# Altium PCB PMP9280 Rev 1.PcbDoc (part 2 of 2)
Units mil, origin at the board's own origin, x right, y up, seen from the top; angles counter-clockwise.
Board outline 4050 x 2360 mil, 4 copper layers (Top Layer, MidLayer1, MidLayer2, Bottom Layer), stack 61.2 mil thick; 80 components, 27 nets, 139 pads, 275 vias.
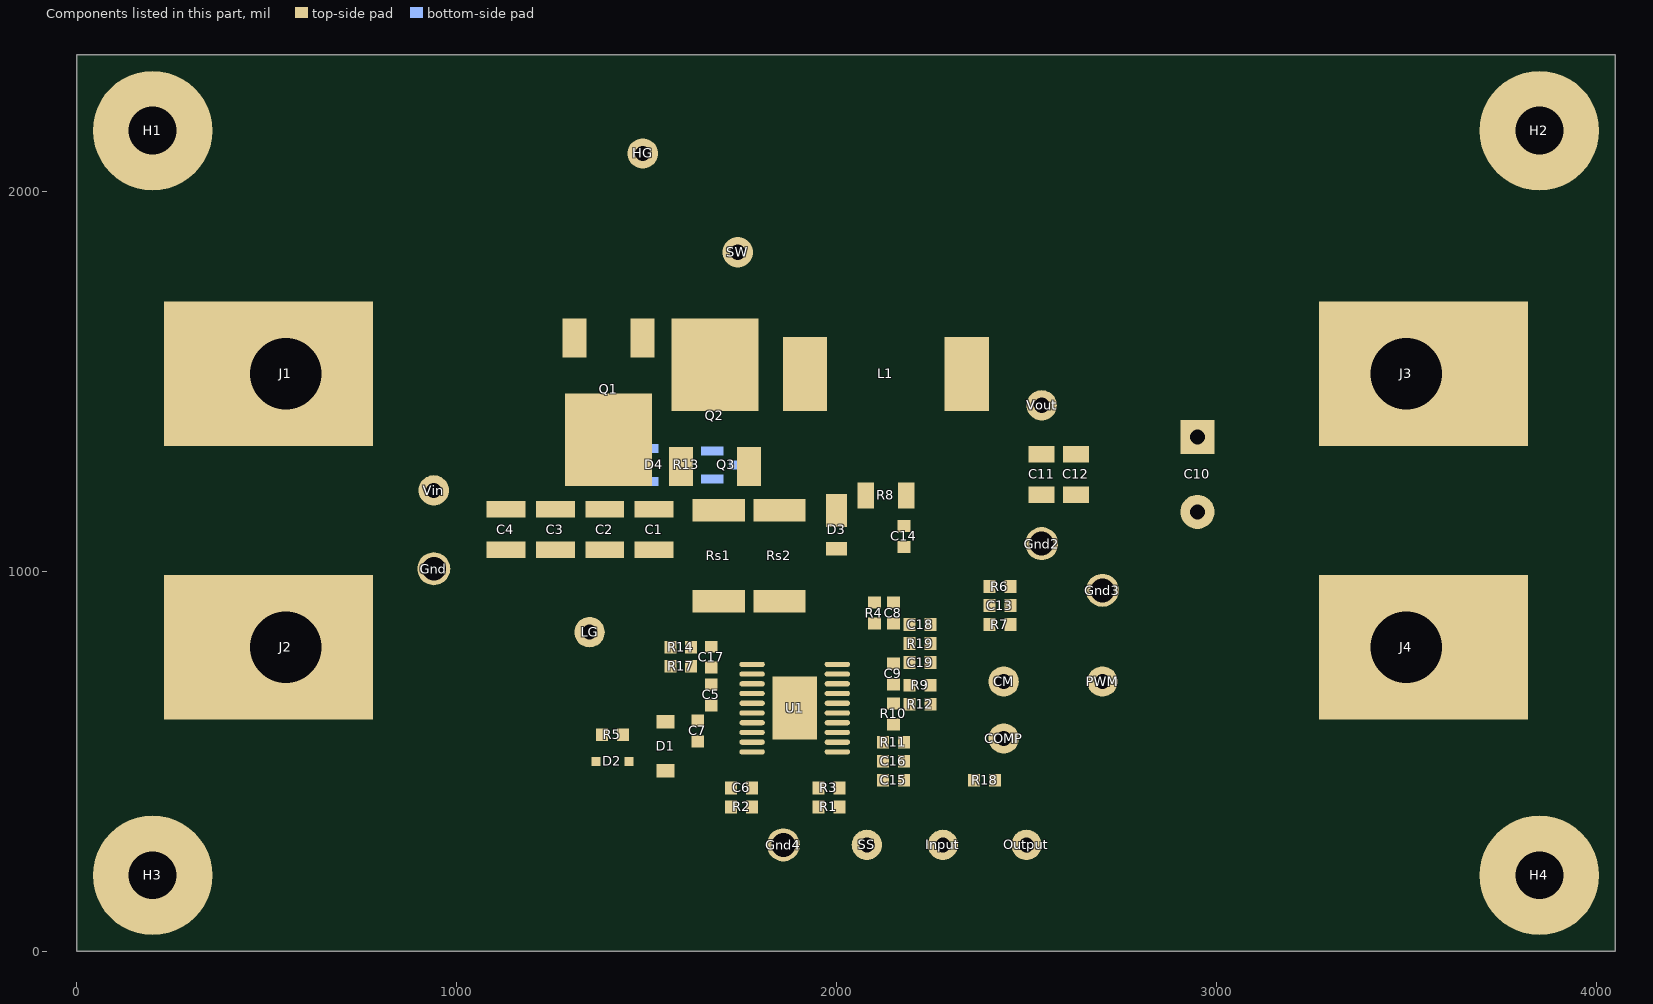
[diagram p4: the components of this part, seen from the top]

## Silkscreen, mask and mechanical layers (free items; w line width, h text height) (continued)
M12 Stackup:
  drawing of 295 lines, arcs and shapes, not listed
  text "Layer" at 5943.24,4323.04 h60
  text "Name" at 6353.15,4323.04 h60
  text "Material" at 7282.9,4323.04 h60
  text "Thickness" at 8142.66,4323.04 h60
  text "Constant" at 8792.5,4323.04 h60
  text "Board Layer Stack" at 9362.36,4323.04 h60
  text "1" at 5943.24,4203.04 h60
  text "Top Overlay" at 6353.15,4203.04 h60
  text "2" at 5943.24,4083.04 h60
  text "Top Solder" at 6353.15,4083.04 h60
  text "Solder Resist" at 7282.9,4083.04 h60
  text "0.40mil" at 8142.66,4083.04 h60
  text "3.5" at 8792.5,4083.04 h60
  text "3" at 5943.24,3963.04 h60
  text "Top Layer" at 6353.15,3963.04 h60
  text "Copper" at 7282.9,3963.04 h60
  text "1.40mil" at 8142.66,3963.04 h60
  text "4" at 5943.24,3843.04 h60
  text "Dielectric1" at 6353.15,3843.04 h60
  text "FR-4" at 7282.9,3843.04 h60
  text "12.60mil" at 8142.66,3843.04 h60
  text "4.8" at 8792.5,3843.04 h60
  text "5" at 5943.24,3723.04 h60
  text "MidLayer1" at 6353.15,3723.04 h60
  text "Copper" at 7282.9,3723.04 h60
  text "1.40mil" at 8142.66,3723.04 h60
  text "6" at 5943.24,3603.04 h60
  text "Dielectric2" at 6353.15,3603.04 h60
  text "FR-4" at 7282.9,3603.04 h60
  text "30.40mil" at 8142.66,3603.04 h60
  text "4.8" at 8792.5,3603.04 h60
  text "7" at 5943.24,3483.04 h60
  text "MidLayer2" at 6353.15,3483.04 h60
  text "Copper" at 7282.9,3483.04 h60
  text "1.40mil" at 8142.66,3483.04 h60
  text "8" at 5943.24,3363.04 h60
  text "Dielectric3" at 6353.15,3363.04 h60
  text "FR-4" at 7282.9,3363.04 h60
  text "12.60mil" at 8142.66,3363.04 h60
  text "4.8" at 8792.5,3363.04 h60
  text "9" at 5943.24,3243.04 h60
  text "Bottom Layer" at 6353.15,3243.04 h60
  text "Copper" at 7282.9,3243.04 h60
  text "1.40mil" at 8142.66,3243.04 h60
  text "10" at 5943.24,3123.04 h60
  text "Bottom Solder" at 6353.15,3123.04 h60
  text "Solder Resist" at 7282.9,3123.04 h60
  text "0.40mil" at 8142.66,3123.04 h60
  text "3.5" at 8792.5,3123.04 h60
  text "11" at 5943.24,3003.04 h60
  text "Bottom Overlay" at 6353.15,3003.04 h60
  text ".Layer_Name" at 17,-1418.49 h60
M13 Component Bodies Top:
  text ".Layer_Name" at 17,-1418.49 h60
M14 Component Bodies Bottom:
  text ".Layer_Name" at 17,-1418.49 h60
M15 Courtyards Top:
  text ".Layer_Name" at 17,-1418.49 h60
M16 Courtyards Bottom:
  text ".Layer_Name" at 17,-1418.49 h60
Drill Drawing:
  circle w10: c4856.73,1551.58 r16.58
  circle w10: c4856.73,1551.58 r27.63
  lines w10: 4829.1,1330.54 4884.36,1330.54 4856.73,1275.28 4829.1,1330.54 ; 4829.1,1413.43 4842.91,1413.43 4856.73,1399.62 4870.54,1413.43 4884.36,1413.43 4870.54,1427.25 4884.36,1441.06 4870.54,1441.06 4856.73,1454.88 4842.91,1441.06 4829.1,1441.06 4842.91,1427.25 4829.1,1413.43 ; 4829.1,1648.29 4884.36,1648.29 4884.36,1703.55 4829.1,1703.55 4829.1,1648.29 ; 4829.1,1786.44 4842.91,1786.44 4842.91,1772.62 4870.54,1772.62 4870.54,1786.44 4884.36,1786.44 4884.36,1814.07 4870.54,1814.07 4870.54,1827.89 4842.91,1827.89 4842.91,1814.07 4829.1,1814.07 4829.1,1786.44 ; 4829.1,2021.3 4829.1,2035.11 4842.91,2048.93 4829.1,2062.74 4829.1,2076.56 4842.91,2076.56 4856.73,2062.74 4870.54,2076.56 4884.36,2076.56 4884.36,2062.74 4870.54,2048.93 4884.36,2035.11 4884.36,2021.3 4870.54,2021.3 4856.73,2035.11 4842.91,2021.3 4829.1,2021.3 ; 4829.1,2145.63 4856.73,2159.45 4884.36,2145.63 4870.54,2173.26 4884.36,2200.89 4856.73,2187.08 4829.1,2200.89 4842.91,2173.26 4829.1,2145.63 ; 4840.15,1319.49 4873.3,1319.49 4856.73,1286.34 4840.15,1319.49 ; 4840.15,1418.96 4848.44,1418.96 4856.73,1410.67 4865.02,1418.96 4873.3,1418.96 4865.02,1427.25 4873.3,1435.54 4865.02,1435.54 4856.73,1443.83 4848.44,1435.54 4840.15,1435.54 4848.44,1427.25 4840.15,1418.96 ; 4840.15,1659.34 4873.3,1659.34 4873.3,1692.5 4840.15,1692.5 4840.15,1659.34 ; 4840.15,1791.97 4848.44,1791.97 4848.44,1783.68 4865.02,1783.68 4865.02,1791.97 4873.3,1791.97 4873.3,1808.54 4865.02,1808.54 4865.02,1816.83 4848.44,1816.83 4848.44,1808.54 4840.15,1808.54 4840.15,1791.97 ; 4840.15,2032.35 4840.15,2040.64 4848.44,2048.93 4840.15,2057.21 4840.15,2065.5 4848.44,2065.5 4856.73,2057.21 4865.02,2065.5 4873.3,2065.5 4873.3,2057.21 4865.02,2048.93 4873.3,2040.64 4873.3,2032.35 4865.02,2032.35 4856.73,2040.64 4848.44,2032.35 4840.15,2032.35 ; 4840.15,2156.68 4856.73,2164.97 4873.3,2156.68 4865.02,2173.26 4873.3,2189.84 4856.73,2181.55 4840.15,2189.84 4848.44,2173.26 4840.15,2156.68
  lines w12: 4779,1237.98 6755.94,1237.98 ; 4779,2232.66 6755.94,2232.66 ; 5116.75,1113.65 5116.75,2357 ; 5448.56,1113.65 5448.56,2357 ; 6084.66,1113.65 6084.66,2357 ; 6343.66,1113.65 6343.66,2357 ; 4779,1113.65 6755.94,1113.65 6755.94,2357 4779,2357 4779,1113.65
  text "Symbol" at 4853.6,2269.97 h72
  text "Quantity" at 5154.05,2269.97 h72
  text "Finished Hole Size" at 5485.86,2269.97 h72
  text "Plated" at 6121.96,2269.97 h72
  text "Hole Type" at 6380.96,2269.97 h72
  text "100" at 5154.05,2145.63 h60
  text "10.00mil (0.254mm)" at 5485.86,2145.63 h60
  text "PTH" at 6121.96,2145.63 h60
  text "Round" at 6380.96,2145.63 h60
  text "58" at 5154.05,2021.3 h60
  text "12.00mil (0.305mm)" at 5485.86,2021.3 h60
  text "PTH" at 6121.96,2021.3 h60
  text "Round" at 6380.96,2021.3 h60
  text "5" at 5154.05,1896.96 h60
  text "15.00mil (0.381mm)" at 5485.86,1896.96 h60
  text "PTH" at 6121.96,1896.96 h60
  text "Round" at 6380.96,1896.96 h60
  text "A" at 4828.31,1886.97 h55.26
  text "112" at 5154.05,1772.62 h60
  text "16.00mil (0.406mm)" at 5485.86,1772.62 h60
  text "PTH" at 6121.96,1772.62 h60
  text "Round" at 6380.96,1772.62 h60
  text "13" at 5154.05,1648.29 h60
  text "40.00mil (1.016mm)" at 5485.86,1648.29 h60
  text "PTH" at 6121.96,1648.29 h60
  text "Round" at 6380.96,1648.29 h60
  text "4" at 5154.05,1523.95 h60
  text "63.00mil (1.600mm)" at 5485.86,1523.95 h60
  text "PTH" at 6121.96,1523.95 h60
  text "Round" at 6380.96,1523.95 h60
  text "4" at 5154.05,1399.62 h60
  text "125.98mil (3.200mm)" at 5485.86,1399.62 h60
  text "PTH" at 6121.96,1399.62 h60
  text "Round" at 6380.96,1399.62 h60
  text "4" at 5154.05,1275.28 h60
  text "188.00mil (4.775mm)" at 5485.86,1275.28 h60
  text "PTH" at 6121.96,1275.28 h60
  text "Round" at 6380.96,1275.28 h60
  text "300 Total" at 5154.05,1150.95 h60
  text ".Layer_Name" at 17,-1418.49 h60

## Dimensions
0,0 to 4050,0 on M2 Board Dimensions
0,0 to 0,2360 on M2 Board Dimensions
